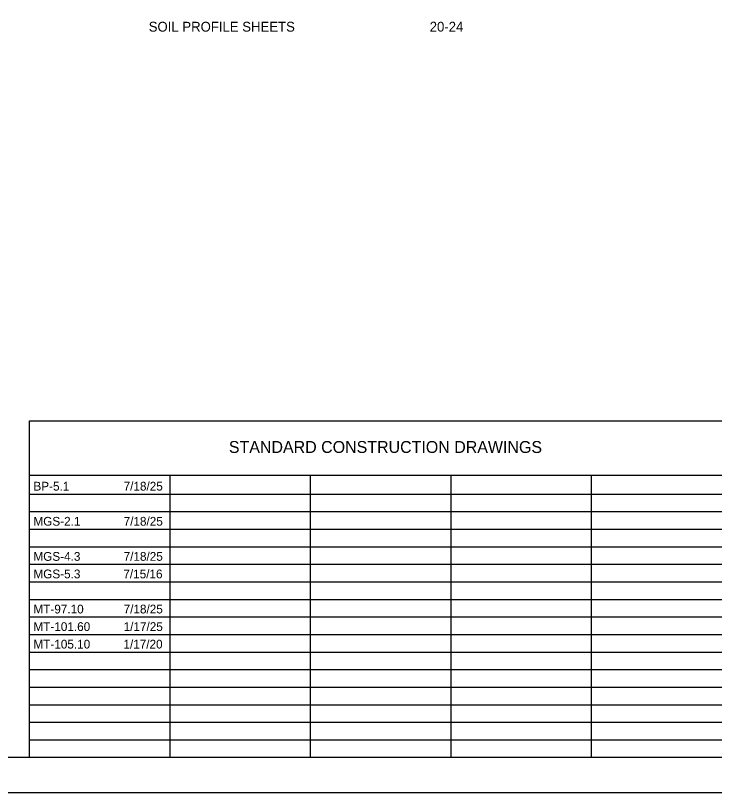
# Model space of a CAD drawing. Extents: x 36.7 to 70.7, y 0 to 22.
# Drawn here: x 46.64 to 56.59, y 0 to 11.06 of the extents above; entities that cross this region are included whole.
import ezdxf

# ---------------------------------------------------------------- set-up
doc = ezdxf.new("R2010")
doc.units = 0
for name, color, linetype in [('Default', 7, 'Continuous'), ('SH_Border', 7, 'Continuous'), ('SH_Cut_Line', 7, 'Continuous'), ('SH_Data', 7, 'Continuous'), ('SH_Text', 7, 'Continuous')]:
    doc.layers.add(name, color=color, linetype=linetype)

msp = doc.modelspace()

# ---------------------------------------------------------------- linework, layer by layer
at = {"layer": 'SH_Border'}
msp.add_lwpolyline([(38.193, 21.497), (70.193, 21.497), (70.193, 0.497), (38.193, 0.497)], close=True, dxfattribs=at)
at = {"layer": 'SH_Cut_Line'}
msp.add_lwpolyline([(36.693, -0.003), (70.693, -0.003), (70.693, 21.997), (36.693, 21.997)], close=True, dxfattribs=at)
at = {"layer": 'SH_Data'}
for p, q in [((46.843, 5.289), (60.293, 5.289)), ((46.843, 0.497), (46.843, 5.289)), ((46.843, 4.518), (60.293, 4.518)), ((48.843, 0.497), (48.843, 4.518)), ((50.843, 0.497), (50.843, 4.518)), ((52.843, 0.497), (52.843, 4.518)), ((54.843, 0.497), (54.843, 4.518)), ((46.843, 4.247), (60.293, 4.247)), ((46.843, 3.997), (60.293, 3.997)), ((46.843, 3.747), (60.293, 3.747)), ((46.843, 3.497), (60.293, 3.497)), ((46.843, 3.247), (60.293, 3.247)), ((46.843, 2.997), (60.293, 2.997)), ((46.843, 2.747), (60.293, 2.747)), ((46.843, 2.497), (60.293, 2.497)), ((46.843, 2.247), (60.293, 2.247)), ((46.843, 1.997), (60.293, 1.997)), ((46.843, 1.747), (60.293, 1.747)), ((46.843, 1.497), (60.293, 1.497)), ((46.843, 1.247), (60.293, 1.247)), ((46.843, 0.997), (60.293, 0.997)), ((46.843, 0.747), (60.293, 0.747))]:
    msp.add_line(p, q, dxfattribs=at)

# ---------------------------------------------------------------- texts
at = {"layer": 'Default'}
for s, p in [('7/18/25', (48.181, 4.297)), ('BP-5.1', (46.897, 4.297)), ('MGS-2.1', (46.897, 3.797)), ('7/18/25', (48.181, 3.797)), ('MGS-4.3', (46.897, 3.297)), ('7/18/25', (48.181, 3.297)), ('MGS-5.3', (46.897, 3.047)), ('7/15/16', (48.177, 3.047)), ('MT-97.10', (46.897, 2.547)), ('7/18/25', (48.181, 2.547)), ('MT-101.60', (46.897, 2.297)), ('1/17/25', (48.181, 2.297)), ('MT-105.10', (46.897, 2.047)), ('1/17/20', (48.178, 2.047))]:
    msp.add_text(s, height=0.125, dxfattribs=at).set_placement(p)
at = {"layer": 'SH_Text'}
for s, height, p in [('SOIL PROFILE SHEETS', 0.14, (48.538, 10.835)), ('20-24', 0.14, (52.538, 10.835)), ('STANDARD CONSTRUCTION DRAWINGS', 0.17, (49.679, 4.833))]:
    msp.add_text(s, height=height, dxfattribs=at).set_placement(p)

doc.saveas('drawing.dxf')
